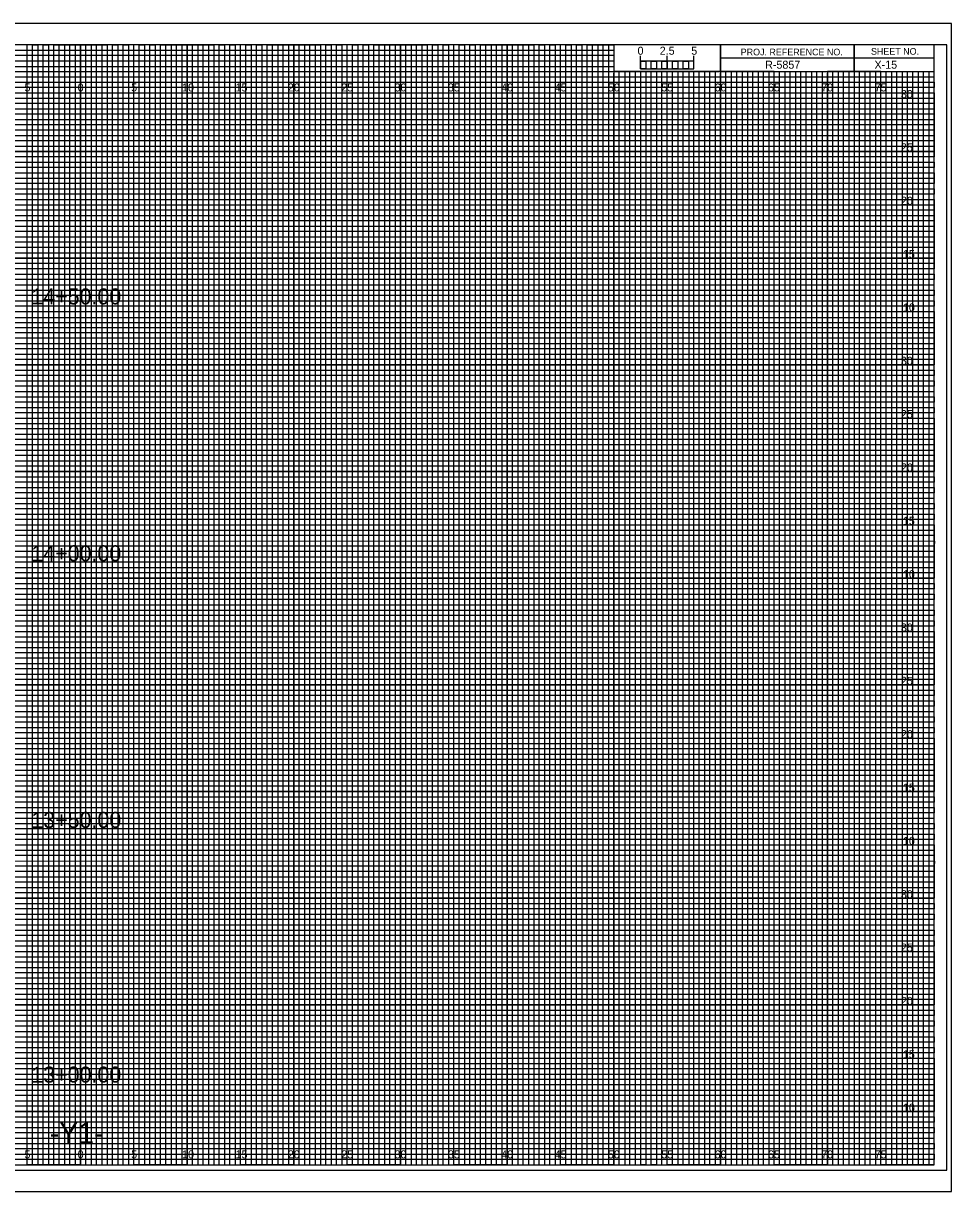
# Model space of a CAD drawing. Extents: x -7 to 162, y 107 to 217.
# Drawn here: x 74.6 to 161.7, y 107.5 to 217 of the extents above; entities that cross this region are included whole.
import ezdxf

# ---------------------------------------------------------------- set-up
doc = ezdxf.new("R2010")
doc.units = 0
for name, color, linetype in [('Exist Cross Section Cell', 7, 'Continuous'), ('Exist XS Center Line Elevation Label', 7, 'Continuous'), ('Exist XS Ground Line', 7, 'Continuous'), ('Prop CMT Pvmt Course 1', 7, 'Continuous'), ('Prop CMT Pvmt Course 1 Wedge', 7, 'Continuous'), ('Prop CMT Pvmt Course 2', 7, 'Continuous'), ('Prop CMT Pvmt Course 2 Wedge', 7, 'Continuous'), ('Prop CMT Pvmt Course 3', 7, 'Continuous'), ('Prop CMT Pvmt Course 3 Wedge', 7, 'Continuous'), ('Prop CMT Pvmt Surface', 7, 'Continuous'), ('Prop CMT Pvmt Surface Shoulder', 7, 'Continuous'), ('Prop CMT Shld Paved Course 1', 7, 'Continuous'), ('Prop CMT Shld Paved Course 2', 7, 'Continuous'), ('Prop CMT Shld Paved Course 3', 7, 'Continuous'), ('Prop CMT Slope Grass', 7, 'Continuous'), ('Prop CMT Subgrade Earthwork', 7, 'Continuous'), ('Scratch_Level_0', 7, 'Continuous')]:
    doc.layers.add(name, color=color, linetype=linetype)

msp = doc.modelspace()

# ---------------------------------------------------------------- linework, layer by layer
at = {"layer": 'Exist XS Center Line Elevation Label'}
for points in [[(72.5, 110), (77.5, 110), (77.5, 215), (82.5, 215), (82.5, 110), (87.5, 110), (87.5, 215), (92.5, 215), (92.5, 110), (97.5, 110), (97.5, 215), (102.5, 215), (102.5, 110), (107.5, 110), (107.5, 215), (112.5, 215), (112.5, 110), (117.5, 110), (117.5, 215), (122.5, 215), (122.5, 110), (127.5, 110), (127.5, 215), (129.97, 215), (130, 215), (130, 212.5), (132.5, 212.5), (132.5, 110), (137.5, 110), (137.5, 212.5), (142.5, 212.5), (142.5, 110), (147.5, 110), (147.5, 212.5), (152.5, 212.5), (152.5, 110), (157.5, 110), (157.5, 212.5)], [(0, 212.5), (137.5, 212.5)], [(0, 202.5), (160, 202.5), (160, 207.5), (0, 207.5)], [(0, 192.5), (160, 192.5), (160, 197.5), (0, 197.5)], [(0, 182.5), (160, 182.5), (160, 187.5), (0, 187.5)], [(0, 172.5), (160, 172.5), (160, 177.5), (0, 177.5)], [(0, 162.5), (160, 162.5), (160, 167.5), (0, 167.5)], [(0, 152.5), (160, 152.5), (160, 157.5), (0, 157.5)], [(0, 142.5), (160, 142.5), (160, 147.5), (0, 147.5)], [(0, 132.5), (160, 132.5), (160, 137.5), (0, 137.5)], [(0, 122.5), (160, 122.5), (160, 127.5), (0, 127.5)], [(0, 112.5), (160, 112.5), (160, 117.5), (0, 117.5)]]:
    msp.add_lwpolyline(points, dxfattribs=at)
at = {"layer": 'Exist XS Ground Line'}
for p, q in [((75, 215), (70, 215)), ((75, 110), (75, 215)), ((85, 215), (80, 215)), ((80, 215), (80, 110)), ((85, 110), (85, 215)), ((95, 215), (90, 215)), ((90, 215), (90, 110)), ((95, 110), (95, 215)), ((105, 215), (100, 215)), ((100, 215), (100, 110)), ((105, 110), (105, 215)), ((115, 215), (110, 215)), ((110, 215), (110, 110)), ((115, 110), (115, 215)), ((125, 215), (120, 215)), ((120, 215), (120, 110)), ((125, 110), (125, 215)), ((130, 215), (130, 110)), ((135, 110), (135, 212.5)), ((145, 212.5), (140, 212.5)), ((140, 212.5), (140, 110)), ((145, 110), (145, 212.5)), ((155, 212.5), (150, 212.5)), ((150, 212.5), (150, 110)), ((155, 110), (155, 212.5)), ((80, 110), (75, 110)), ((90, 110), (85, 110)), ((100, 110), (95, 110)), ((110, 110), (105, 110)), ((120, 110), (115, 110)), ((130, 110), (125, 110)), ((140, 110), (135, 110)), ((150, 110), (145, 110)), ((160, 110), (155, 110)), ((160, 110), (160, 110))]:
    msp.add_line(p, q, dxfattribs=at)
for points in [[(0, 210), (160, 210), (160, 205), (0, 205)], [(0, 200), (160, 200), (160, 195), (0, 195)], [(0, 190), (160, 190), (160, 185), (0, 185)], [(0, 180), (160, 180), (160, 175), (0, 175)], [(0, 170), (160, 170), (160, 165), (0, 165)], [(0, 160), (160, 160), (160, 155), (0, 155)], [(0, 150), (160, 150), (160, 145), (0, 145)], [(0, 140), (160, 140), (160, 135), (0, 135)], [(0, 130), (160, 130), (160, 125), (0, 125)], [(0, 120), (160, 120), (160, 115), (0, 115)]]:
    msp.add_lwpolyline(points, dxfattribs=at)
at = {"layer": 'Prop CMT Pvmt Course 2'}
msp.add_lwpolyline([(-6.7, 107.5), (161.65, 107.5), (161.65, 217), (-6.7, 217)], close=True, dxfattribs=at)
at = {"layer": 'Prop CMT Pvmt Course 3'}
msp.add_lwpolyline([(-5.4, 109.5), (161.2, 109.5), (161.2, 215), (-5.4, 215)], close=True, dxfattribs=at)
at = {"layer": 'Prop CMT Pvmt Surface'}
for p, q in [((161.65, 217), (-6.7, 217)), ((-6.7, 107.5), (161.65, 107.5))]:
    msp.add_line(p, q, dxfattribs=at)
at = {"layer": 'Prop CMT Shld Paved Course 1'}
for p, q in [((152.5, 215), (152.5, 212.5)), ((152.5, 212.5), (152.5, 215)), ((160, 213.75), (140, 213.75)), ((140, 213.75), (140, 212.5)), ((140, 212.5), (160, 212.5))]:
    msp.add_line(p, q, dxfattribs=at)
for points in [[(160, 215), (0, 215), (0, 110), (160, 110)], [(140, 215), (130, 215), (130, 212.52), (140, 212.52)], [(160, 215), (140, 215), (140, 212.5), (160, 212.5)]]:
    msp.add_lwpolyline(points, close=True, dxfattribs=at)
at = {"layer": 'Prop CMT Shld Paved Course 2'}
for p, q in [((133.5, 212.5), (133, 212.5)), ((133, 212.5), (133, 110)), ((133.5, 110), (133.5, 212.5)), ((134.5, 212.5), (134, 212.5)), ((134, 212.5), (134, 110)), ((134.5, 110), (134.5, 212.5)), ((133, 110), (132.5, 110)), ((134, 110), (133.5, 110))]:
    msp.add_line(p, q, dxfattribs=at)
for points in [[(75, 110), (75.5, 110), (75.5, 215), (76, 215), (76, 110)], [(76, 110), (76.5, 110), (76.5, 215), (77, 215), (77, 110)], [(77.5, 110), (78, 110), (78, 215), (78.5, 215), (78.5, 110)], [(78.5, 110), (79, 110), (79, 215), (79.5, 215), (79.5, 110)], [(80, 110), (80.5, 110), (80.5, 215), (81, 215), (81, 110)], [(81, 110), (81.5, 110), (81.5, 215), (82, 215), (82, 110)], [(82.5, 110), (83, 110), (83, 215), (83.5, 215), (83.5, 110)], [(83.5, 110), (84, 110), (84, 215), (84.5, 215), (84.5, 110)], [(85, 110), (85.5, 110), (85.5, 215), (86, 215), (86, 110)], [(86, 110), (86.5, 110), (86.5, 215), (87, 215), (87, 110)], [(87.5, 110), (88, 110), (88, 215), (88.5, 215), (88.5, 110)], [(88.5, 110), (89, 110), (89, 215), (89.5, 215), (89.5, 110)], [(90, 110), (90.5, 110), (90.5, 215), (91, 215), (91, 110)], [(91, 110), (91.5, 110), (91.5, 215), (92, 215), (92, 110)], [(92.5, 110), (93, 110), (93, 215), (93.5, 215), (93.5, 110)], [(93.5, 110), (94, 110), (94, 215), (94.5, 215), (94.5, 110)], [(95, 110), (95.5, 110), (95.5, 215), (96, 215), (96, 110)], [(96, 110), (96.5, 110), (96.5, 215), (97, 215), (97, 110)], [(97.5, 110), (98, 110), (98, 215), (98.5, 215), (98.5, 110)], [(98.5, 110), (99, 110), (99, 215), (99.5, 215), (99.5, 110)], [(100, 110), (100.5, 110), (100.5, 215), (101, 215), (101, 110)], [(101, 110), (101.5, 110), (101.5, 215), (102, 215), (102, 110)], [(102.5, 110), (103, 110), (103, 215), (103.5, 215), (103.5, 110)], [(103.5, 110), (104, 110), (104, 215), (104.5, 215), (104.5, 110)], [(105, 110), (105.5, 110), (105.5, 215), (106, 215), (106, 110)], [(106, 110), (106.5, 110), (106.5, 215), (107, 215), (107, 110)], [(107.5, 110), (108, 110), (108, 215), (108.5, 215), (108.5, 110)], [(108.5, 110), (109, 110), (109, 215), (109.5, 215), (109.5, 110)], [(110, 110), (110.5, 110), (110.5, 215), (111, 215), (111, 110)], [(111, 110), (111.5, 110), (111.5, 215), (112, 215), (112, 110)], [(112.5, 110), (113, 110), (113, 215), (113.5, 215), (113.5, 110)], [(113.5, 110), (114, 110), (114, 215), (114.5, 215), (114.5, 110)], [(115, 110), (115.5, 110), (115.5, 215), (116, 215), (116, 110)], [(116, 110), (116.5, 110), (116.5, 215), (117, 215), (117, 110)], [(117.5, 110), (118, 110), (118, 215), (118.5, 215), (118.5, 110)], [(118.5, 110), (119, 110), (119, 215), (119.5, 215), (119.5, 110)], [(120, 110), (120.5, 110), (120.5, 215), (121, 215), (121, 110)], [(121, 110), (121.5, 110), (121.5, 215), (122, 215), (122, 110)], [(122.5, 110), (123, 110), (123, 215), (123.5, 215), (123.5, 110)], [(123.5, 110), (124, 110), (124, 215), (124.5, 215), (124.5, 110)], [(125, 110), (125.5, 110), (125.5, 215), (126, 215), (126, 110)], [(126, 110), (126.5, 110), (126.5, 215), (127, 215), (127, 110)], [(127.5, 110), (128, 110), (128, 215), (128.5, 215), (128.5, 110)], [(128.5, 110), (129, 110), (129, 215), (129.5, 215), (129.5, 110)], [(130, 110), (130.5, 110), (130.5, 212.5), (131.01, 212.5), (131.01, 110)], [(131, 110), (131.5, 110), (131.5, 212.5), (132, 212.5), (132, 110)], [(135, 110), (135.49, 110), (135.49, 212.5), (136, 212.5), (136, 110)], [(136, 110), (136.5, 110), (136.5, 212.5), (137.03, 212.5), (137.03, 110)], [(137.5, 110), (138, 110), (138, 212.5), (138.5, 212.5), (138.5, 110)], [(138.5, 110), (139, 110), (139, 212.5), (139.5, 212.5), (139.5, 110)], [(140, 110), (140.5, 110), (140.5, 212.5), (141, 212.5), (141, 110)], [(141, 110), (141.5, 110), (141.5, 212.5), (142, 212.5), (142, 110)], [(142.5, 110), (143, 110), (143, 212.5), (143.5, 212.5), (143.5, 110)], [(143.5, 110), (144, 110), (144, 212.5), (144.5, 212.5), (144.5, 110)], [(145, 110), (145.5, 110), (145.5, 212.5), (146, 212.5), (146, 110)], [(146, 110), (146.5, 110), (146.5, 212.5), (147, 212.5), (147, 110)], [(147.5, 110), (148, 110), (148, 212.5), (148.5, 212.5), (148.5, 110)], [(148.5, 110), (149, 110), (149, 212.5), (149.5, 212.5), (149.5, 110)], [(150, 110), (150.5, 110), (150.5, 212.5), (151, 212.5), (151, 110)], [(151, 110), (151.5, 110), (151.5, 212.5), (152, 212.5), (152, 110)], [(152.5, 110), (153, 110), (153, 212.5), (153.5, 212.5), (153.5, 110)], [(153.5, 110), (154, 110), (154, 212.5), (154.5, 212.5), (154.5, 110)], [(155, 110), (155.5, 110), (155.5, 212.5), (156, 212.5), (156, 110)], [(156, 110), (156.5, 110), (156.5, 212.5), (157, 212.5), (157, 110)], [(157.5, 110), (158, 110), (158, 212.5), (158.5, 212.5), (158.5, 110)], [(158.5, 110), (159, 110), (159, 212.5), (159.5, 212.5), (159.5, 110)]]:
    msp.add_lwpolyline(points, dxfattribs=at)
at = {"layer": 'Prop CMT Shld Paved Course 3'}
for p, q in [((132.5, 212.75), (132.5, 213.95)), ((132.5, 213.45), (132.5, 213.95)), ((135, 212.75), (135, 213.95)), ((137.5, 212.75), (137.5, 213.95)), ((137.5, 213.45), (137.5, 213.95))]:
    msp.add_line(p, q, dxfattribs=at)
for points in [[(137.5, 213.45), (132.5, 213.45), (132.5, 212.75), (137.5, 212.75)], [(132.5, 213.45), (133, 213.45), (133, 212.75), (132.5, 212.75)], [(133.5, 213.45), (134, 213.45), (134, 212.75), (133.5, 212.75)], [(134.5, 213.45), (135, 213.45), (135, 212.75), (134.5, 212.75)], [(135.5, 213.45), (136, 213.45), (136, 212.75), (135.5, 212.75)], [(136.5, 213.45), (137, 213.45), (137, 212.75), (136.5, 212.75)]]:
    msp.add_lwpolyline(points, close=True, dxfattribs=at)
at = {"layer": 'Prop CMT Subgrade Earthwork'}
for p, q in [((75, 110), (75, 215)), ((80, 110), (80, 215)), ((85, 110), (85, 215)), ((90, 110), (90, 215)), ((95, 110), (95, 215)), ((100, 110), (100, 215)), ((105, 110), (105, 215)), ((110, 110), (110, 215)), ((115, 110), (115, 215)), ((120, 110), (120, 215)), ((125, 110), (125, 215)), ((130, 110), (130, 212.34)), ((135, 110), (135, 212.34)), ((140, 110), (140, 212.34)), ((145, 110), (145, 212.34)), ((150, 110), (150, 212.34)), ((155, 110), (155, 212.34)), ((0, 210), (160, 210)), ((0, 205), (160, 205)), ((0, 200), (160, 200)), ((0, 195), (160, 195)), ((0, 190), (160, 190)), ((0, 185), (160, 185)), ((0, 180), (160, 180)), ((0, 175), (160, 175)), ((0, 170), (160, 170)), ((0, 165), (160, 165)), ((0, 160), (160, 160)), ((0, 155), (160, 155)), ((0, 150), (160, 150)), ((0, 145), (160, 145)), ((0, 140), (160, 140)), ((0, 135), (160, 135)), ((0, 130), (160, 130)), ((0, 125), (160, 125)), ((0, 120), (160, 120)), ((0, 115), (160, 115))]:
    msp.add_line(p, q, dxfattribs=at)
at = {"layer": 'Scratch_Level_0'}
for p, q in [((0, 214.5), (130, 214.5)), ((130, 213.99), (0, 213.99)), ((130, 214.5), (130, 213.99)), ((0, 213.5), (130, 213.5)), ((130, 212.94), (0, 212.94)), ((130, 213.5), (130, 212.94)), ((0, 212), (160, 212))]:
    msp.add_line(p, q, dxfattribs=at)
for points in [[(0, 211.5), (135, 211.5), (160, 211.5), (160, 211), (0, 211)], [(0, 210.5), (160, 210.5), (160, 209.5), (0, 209.5)], [(0, 209), (160, 209), (160, 208.5), (0, 208.49)], [(0, 208), (160, 208), (160, 207), (0, 207)], [(0, 206.5), (160, 206.5), (160, 206), (0, 206)], [(0, 205.5), (160, 205.5), (160, 204.5), (0, 204.5)], [(0, 204), (160, 204), (160, 203.5), (0, 203.5)], [(0, 203), (160, 203), (160, 202), (0, 202)], [(0, 201.5), (160, 201.5), (160, 201), (0, 201)], [(0, 200.5), (160, 200.5), (160, 199.5), (0, 199.5)], [(0, 199), (160, 199), (160, 198.5), (0, 198.5)], [(0, 198), (160, 198), (160, 196.97), (160, 196.5), (160, 196), (0, 196)], [(0, 197), (160, 197), (160, 196.5), (0, 196.5)], [(0, 195.5), (160, 195.5), (160, 194.5), (0, 194.52)], [(0, 194.52), (160, 194.5), (160, 194), (0, 194)], [(0, 193.5), (160, 193.5), (160, 193), (0, 193)], [(0, 192), (160, 192), (160, 191.5), (0, 191.5)], [(0, 191), (160, 191), (160, 190.5), (0, 190.5)], [(-0.04, 189.44), (160, 189.44), (160, 188.94), (-0.04, 188.94)], [(0, 188.5), (160, 188.5), (160, 188), (0, 188)], [(0, 187), (160, 187), (160, 186.5), (0, 186.5)], [(0, 186), (160, 186), (160, 185.5), (0, 185.5)], [(0, 184.5), (160, 184.5), (160, 184), (0, 184)], [(0, 183.5), (160, 183.5), (160, 183), (0, 183)], [(0, 182), (160, 182), (160, 181.5), (0, 181.5)], [(0, 181), (160, 181), (160, 180.5), (0, 180.5)], [(0, 179.5), (160, 179.5), (160, 178.99), (0, 179)], [(0, 178.5), (160, 178.5), (160, 178), (0, 178)], [(0, 177), (160, 177), (160, 176.5), (0, 176.5)], [(0, 176), (160, 176), (160, 175.5), (0, 175.5)], [(0, 174.5), (160, 174.5), (160, 174), (0, 174)], [(0, 173.5), (160, 173.5), (160, 173), (0, 173)], [(0, 172), (160, 172), (160, 171.5), (0, 171.5)], [(0, 171), (160, 171), (160, 170.5), (0, 170.5)], [(0, 169.5), (160, 169.5), (160, 169), (0, 169)], [(0, 168.5), (160.03, 168.46), (160, 168), (0, 168)], [(0, 167), (160, 167), (160, 166.5), (0, 166.5)], [(0, 166), (160, 166), (160, 165.5), (0, 165.5)], [(0, 164.5), (160, 164.5), (160, 164), (0, 164)], [(0, 163.5), (160, 163.5), (160, 163), (0, 163)], [(0, 162), (160, 162), (160, 161.5), (0, 161.5)], [(0, 161), (160, 161), (160, 160.5), (0, 160.5)], [(0, 159.5), (160, 159.5), (160, 159), (0, 159)], [(0, 158.5), (160, 158.5), (160, 158), (0, 158)], [(0, 157), (160, 157), (160, 156.5), (0, 156.5)], [(0, 156), (160, 156), (160, 155.5), (0, 155.5)], [(0, 154.5), (160, 154.5), (160, 154), (0, 154)], [(0, 153.5), (160, 153.5), (160, 153), (0, 153)], [(0, 152), (160, 152), (160, 151.5), (0, 151.5)], [(0, 151), (160, 151), (160, 150.5), (0, 150.5)], [(0, 149.5), (160, 149.5), (160, 148.99), (0, 149)], [(0, 148.5), (160, 148.5), (160, 148), (0, 148)], [(0, 147), (160, 147), (160, 146.5), (0, 146.5)], [(0, 146), (160, 146), (160, 145.5), (0, 145.5)], [(0, 144.5), (160, 144.5), (160, 144), (0, 144)], [(0, 143.5), (160, 143.5), (160, 143), (0, 143)], [(0, 142), (160, 142), (160, 141.5), (0, 141.5)], [(0, 141), (160, 141), (160, 140.5), (0, 140.5)], [(0, 139.5), (160, 139.5), (160, 139), (0, 139)], [(0, 138.5), (160.03, 138.46), (160, 138), (0, 138)], [(0, 137), (160, 137), (160, 136.5), (0, 136.5)], [(0, 136), (160, 136), (160, 135.5), (0, 135.5)], [(0, 134.5), (160, 134.5), (160, 134), (0, 134)], [(0, 133.5), (160, 133.5), (160, 133), (0, 133)], [(0, 132), (160, 132), (160, 131.5), (0, 131.5)], [(0, 131), (160, 131), (160, 130.5), (0, 130.5)], [(0, 129.5), (160, 129.5), (160, 129), (0, 129)], [(0, 128.5), (160, 128.5), (160, 128), (0, 128)], [(0, 127), (160, 127), (160, 126.5), (0, 126.5)], [(0, 126), (160, 126), (160, 125.5), (0, 125.5)], [(0, 124.5), (160, 124.5), (160, 124), (0, 124)], [(0, 123.5), (160, 123.5), (160, 123), (0, 123)], [(0, 122), (160, 122), (160, 121.5), (0, 121.5)], [(0, 121), (160, 121), (160, 120.5), (0, 120.5)], [(0, 119.5), (160, 119.5), (160, 119), (0, 119)], [(0, 118.5), (160, 118.5), (160, 118), (0, 118)], [(0, 117), (160, 117), (160, 116.5), (0, 116.5)], [(0, 116), (160, 116), (160, 115.5), (0, 115.5)], [(0, 114.5), (160, 114.5), (160, 114), (0, 114)], [(0, 113.5), (160, 113.5), (160, 113), (0, 113)], [(0, 112), (160, 112), (160, 111.5), (0, 111.5)], [(0, 111), (160, 111), (160, 110.5), (0, 110.5)]]:
    msp.add_lwpolyline(points, dxfattribs=at)

# ---------------------------------------------------------------- texts
at = {"layer": 'Exist Cross Section Cell'}
for s, p in [('5', (74.74, 210.62)), ('0', (79.73, 210.62)), ('0', (79.73, 210.62)), ('5', (84.74, 210.62)), ('10', (89.52, 210.62)), ('15', (94.53, 210.62)), ('20', (99.43, 210.62)), ('25', (104.44, 210.62)), ('30', (109.43, 210.62)), ('35', (114.44, 210.62)), ('40', (119.43, 210.62)), ('45', (124.44, 210.62)), ('50', (129.43, 210.62)), ('55', (134.44, 210.62)), ('60', (139.43, 210.62)), ('65', (144.44, 210.62)), ('70', (149.43, 210.62)), ('75', (154.44, 210.62)), ('5', (74.74, 110.62)), ('0', (79.73, 110.62)), ('0', (79.73, 110.62)), ('5', (84.74, 110.62)), ('10', (89.52, 110.62)), ('15', (94.53, 110.62)), ('20', (99.43, 110.62)), ('25', (104.44, 110.62)), ('30', (109.43, 110.62)), ('35', (114.44, 110.62)), ('40', (119.43, 110.62)), ('45', (124.44, 110.62)), ('50', (129.43, 110.62)), ('55', (134.44, 110.62)), ('60', (139.43, 110.62)), ('65', (144.44, 110.62)), ('70', (149.43, 110.62)), ('75', (154.44, 110.62))]:
    msp.add_text(s, height=0.75, dxfattribs=at).set_placement(p)
at = {"layer": 'Prop CMT Pvmt Course 1'}
for s, p in [('14+50.00', (75.39, 190.66)), ('14+00.00', (75.39, 166.58)), ('13+50.00', (75.39, 141.59)), ('13+00.00', (75.39, 117.72))]:
    msp.add_text(s, height=1.5, dxfattribs=at).set_placement(p)
at = {"layer": 'Prop CMT Pvmt Course 1 Wedge'}
msp.add_text('R-5857', height=0.75, dxfattribs=at).set_placement((144.17, 212.75))
at = {"layer": 'Prop CMT Pvmt Course 2 Wedge'}
msp.add_text('-Y1-', height=2, dxfattribs=at).set_placement((77.11, 112))
at = {"layer": 'Prop CMT Pvmt Course 3 Wedge'}
for s, p in [('2.5', (134.29, 214.06)), ('5', (137.24, 214.06))]:
    msp.add_text(s, height=0.75, dxfattribs=at).set_placement(p)
at = {"layer": 'Prop CMT Pvmt Surface Shoulder'}
for s, p in [('30', (156.89, 210)), ('25', (156.89, 205)), ('20', (156.9, 200)), ('15', (157.08, 195)), ('10', (157.09, 190)), ('30', (156.89, 185)), ('25', (156.89, 180)), ('20', (156.9, 175)), ('15', (157.08, 170)), ('10', (157.09, 165)), ('30', (156.89, 160)), ('25', (156.89, 155)), ('20', (156.9, 150)), ('15', (157.08, 145)), ('10', (157.09, 140)), ('30', (156.89, 135)), ('25', (156.89, 130)), ('20', (156.9, 125)), ('15', (157.08, 120)), ('10', (157.09, 115))]:
    msp.add_text(s, height=0.75, dxfattribs=at).set_placement(p)
at = {"layer": 'Prop CMT Shld Paved Course 1'}
for s, p in [('PROJ. REFERENCE NO.', (141.88, 214)), ('SHEET NO.', (154.09, 214.06))]:
    msp.add_text(s, height=0.625, dxfattribs=at).set_placement(p)
at = {"layer": 'Prop CMT Shld Paved Course 3'}
msp.add_text('0', height=0.75, dxfattribs=at).set_placement((132.21, 214.06))
at = {"layer": 'Prop CMT Slope Grass'}
msp.add_text('X-15', height=0.75, dxfattribs=at).set_placement((154.42, 212.75))

doc.saveas('drawing.dxf')
